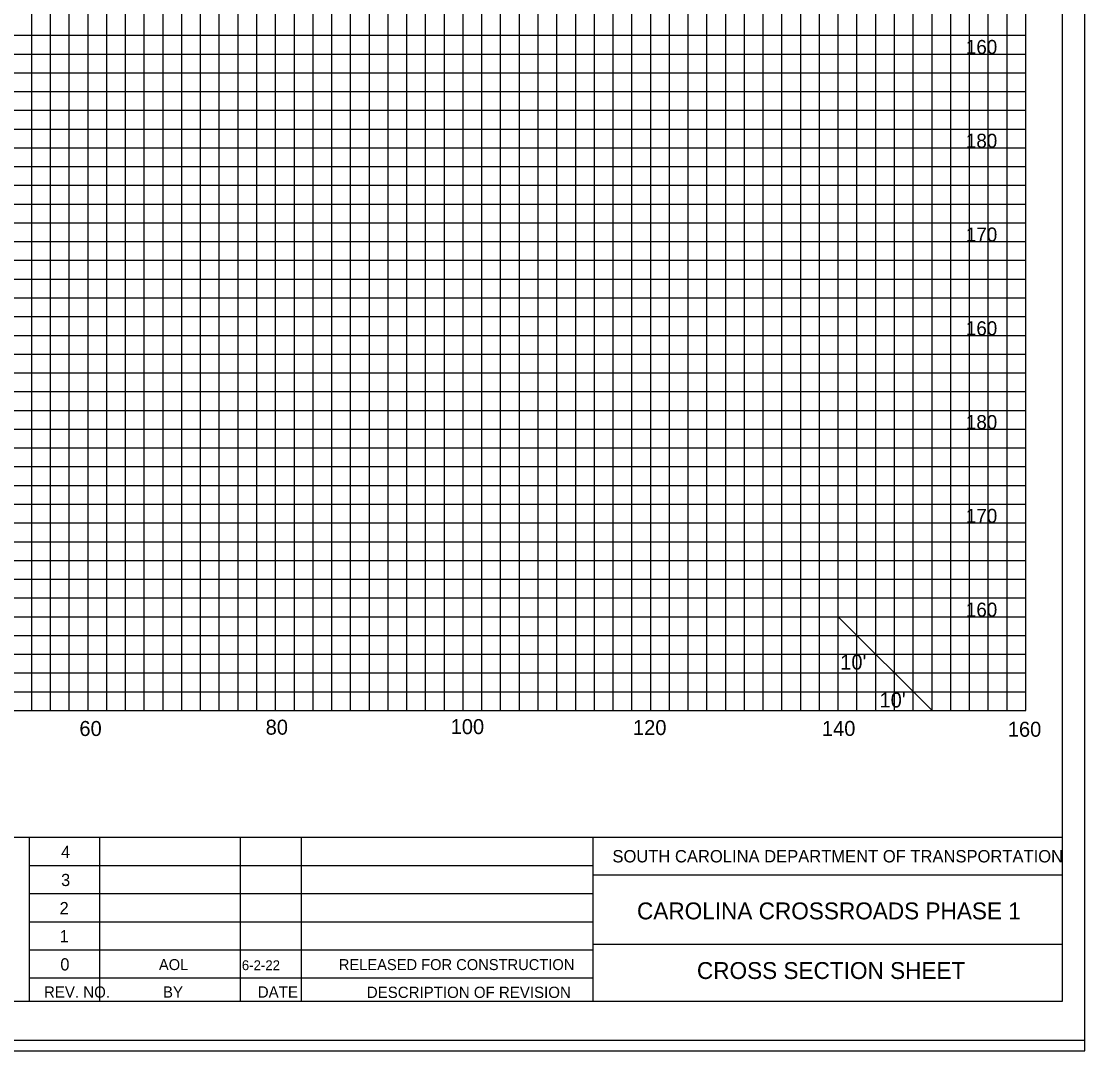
# Model space of a CAD drawing. Extents: x 967 to 1326, y 964 to 2864.
# Drawn here: x 1212.9 to 1326.3, y 2363.7 to 2473.5 of the extents above; entities that cross this region are included whole.
import ezdxf

# ---------------------------------------------------------------- set-up
doc = ezdxf.new("R2010")
doc.units = 0
for name, color, linetype in [('Default', 7, 'Continuous'), ('RD_EX_RW', 7, 'Continuous'), ('RD_PD_Final_TX', 7, 'Continuous'), ('RD_SHT_ShtClip', 7, 'Continuous'), ('RD_XS_TX_Elev_PR', 7, 'Continuous'), ('RD_XS_TX_ShdSlope', 7, 'Continuous'), ('RD_XS_TX_Slope', 7, 'Continuous')]:
    doc.layers.add(name, color=color, linetype=linetype)

msp = doc.modelspace()

# ---------------------------------------------------------------- linework, layer by layer
at = {"layer": 'RD_EX_RW'}
for p, q in [((1220, 2400), (1220, 2570)), ((1230, 2400), (1230, 2570)), ((1240, 2400), (1240, 2570)), ((1250, 2400), (1250, 2570)), ((1260, 2400), (1260, 2570)), ((1270, 2400), (1270, 2570)), ((1280, 2400), (1280, 2570)), ((1290, 2400), (1290, 2570)), ((1300, 2400), (1300, 2570)), ((1310, 2400), (1310, 2570)), ((1320, 2400), (1320, 2570)), ((1000, 2470), (1320, 2470)), ((1000, 2460), (1320, 2460)), ((1000, 2450), (1320, 2450)), ((1000, 2440), (1320, 2440)), ((1000, 2430), (1320, 2430)), ((1000, 2420), (1320, 2420)), ((1000, 2410), (1320, 2410)), ((1000, 2400), (1320, 2400))]:
    msp.add_line(p, q, dxfattribs=at)
at = {"layer": 'RD_PD_Final_TX'}
for p, q in [((1323.89, 2578.46), (1323.89, 2368.98)), ((996.11, 2386.49), (1323.89, 2386.49)), ((1213.76, 2368.94), (1213.76, 2386.49)), ((1221.26, 2368.95), (1221.26, 2386.48)), ((1236.26, 2368.95), (1236.26, 2386.48)), ((1242.76, 2368.95), (1242.76, 2386.48)), ((1273.88, 2368.98), (1273.88, 2386.49)), ((1213.76, 2383.48), (1273.88, 2383.48)), ((1323.93, 2382.43), (1273.88, 2382.43)), ((1213.76, 2380.48), (1273.88, 2380.48)), ((1213.76, 2377.48), (1273.88, 2377.48)), ((1323.89, 2375.04), (1273.88, 2375.04)), ((1213.76, 2374.48), (1273.88, 2374.48)), ((1213.76, 2371.48), (1273.88, 2371.48)), ((1323.89, 2368.98), (996.11, 2368.98))]:
    msp.add_line(p, q, dxfattribs=at)
at = {"layer": 'RD_SHT_ShtClip'}
for p, q in [((1214, 2400), (1214, 2570)), ((1216, 2400), (1216, 2570)), ((1218, 2400), (1218, 2570)), ((1222, 2400), (1222, 2570)), ((1224, 2400), (1224, 2570)), ((1226, 2400), (1226, 2570)), ((1228, 2400), (1228, 2570)), ((1232, 2400), (1232, 2570)), ((1234, 2400), (1234, 2570)), ((1236, 2400), (1236, 2570)), ((1238, 2400), (1238, 2570)), ((1242, 2400), (1242, 2570)), ((1244, 2400), (1244, 2570)), ((1246, 2400), (1246, 2570)), ((1248, 2400), (1248, 2570)), ((1252, 2400), (1252, 2570)), ((1254, 2400), (1254, 2570)), ((1256, 2400), (1256, 2570)), ((1258, 2400), (1258, 2570)), ((1262, 2400), (1262, 2570)), ((1264, 2400), (1264, 2570)), ((1266, 2400), (1266, 2570)), ((1268, 2400), (1268, 2570)), ((1272, 2400), (1272, 2570)), ((1274, 2400), (1274, 2570)), ((1276, 2400), (1276, 2570)), ((1278, 2400), (1278, 2570)), ((1282, 2400), (1282, 2570)), ((1284, 2400), (1284, 2570)), ((1286, 2400), (1286, 2570)), ((1288, 2400), (1288, 2570)), ((1292, 2400), (1292, 2570)), ((1294, 2400), (1294, 2570)), ((1296, 2400), (1296, 2570)), ((1298, 2400), (1298, 2570)), ((1302, 2400), (1302, 2570)), ((1304, 2400), (1304, 2570)), ((1306, 2400), (1306, 2570)), ((1308, 2400), (1308, 2570)), ((1312, 2400), (1312, 2570)), ((1314, 2400), (1314, 2570)), ((1316, 2400), (1316, 2570)), ((1318, 2400), (1318, 2570)), ((1000, 2472), (1320, 2472)), ((1000, 2468), (1320, 2468)), ((1000, 2466), (1320, 2466)), ((1000, 2464), (1320, 2464)), ((1000, 2462), (1320, 2462)), ((1000, 2458), (1320, 2458)), ((1000, 2456), (1320, 2456)), ((1000, 2454), (1320, 2454)), ((1000, 2452), (1320, 2452)), ((1000, 2448), (1320, 2448)), ((1000, 2446), (1320, 2446)), ((1000, 2444), (1320, 2444)), ((1000, 2442), (1320, 2442)), ((1000, 2438), (1320, 2438)), ((1000, 2436), (1320, 2436)), ((1000, 2434), (1320, 2434)), ((1000, 2432), (1320, 2432)), ((1000, 2428), (1320, 2428)), ((1000, 2426), (1320, 2426)), ((1000, 2424), (1320, 2424)), ((1000, 2422), (1320, 2422)), ((1000, 2418), (1320, 2418)), ((1000, 2416), (1320, 2416)), ((1000, 2414), (1320, 2414)), ((1000, 2412), (1320, 2412)), ((1000, 2408), (1320, 2408)), ((1000, 2406), (1320, 2406)), ((1000, 2404), (1320, 2404)), ((1000, 2402), (1320, 2402))]:
    msp.add_line(p, q, dxfattribs=at)
at = {"layer": 'RD_XS_TX_Elev_PR'}
for points in [[(967.41, 2363.72), (1326.28, 2363.72), (1326.28, 2583.72), (967.41, 2583.72)], [(988.52, 2364.84), (1326.28, 2364.84), (1326.28, 2582.6), (988.52, 2582.6)]]:
    msp.add_lwpolyline(points, close=True, dxfattribs=at)
at = {"layer": 'RD_XS_TX_Slope'}
msp.add_line((1300, 2410), (1310, 2400), dxfattribs=at)

# ---------------------------------------------------------------- texts
at = {"layer": 'Default'}
for s, p in [('160', (1313.61, 2470)), ('180', (1313.61, 2460)), ('170', (1313.61, 2450)), ('160', (1313.61, 2440)), ('180', (1313.61, 2430)), ('170', (1313.61, 2420)), ('160', (1313.61, 2410))]:
    msp.add_text(s, height=1.5, dxfattribs=at).set_placement(p)
at = {"layer": 'RD_XS_TX_ShdSlope'}
for s, height, p in [('AOL', 1.17, (1227.56, 2372.32)), ('6-2-22', 1.053, (1236.4, 2372.31)), ('RELEASED FOR CONSTRUCTION', 1.17, (1246.74, 2372.32))]:
    msp.add_text(s, height=height, dxfattribs=at).set_placement(p)
at = {"layer": 'RD_XS_TX_Slope'}
for s, height, p in [("10'", 1.6, (1300.21, 2404.36)), ("10'", 1.6, (1304.4, 2400.32)), ('60', 1.6, (1219.08, 2397.28)), ('80', 1.6, (1238.94, 2397.42)), ('100', 1.6, (1258.67, 2397.48)), ('120', 1.6, (1278.11, 2397.38)), ('140', 1.6, (1298.26, 2397.29)), ('160', 1.6, (1318.08, 2397.2)), ('4', 1.3, (1217.13, 2384.28)), ('SOUTH CAROLINA DEPARTMENT OF TRANSPORTATION', 1.32, (1275.92, 2383.8)), ('3', 1.3, (1217.13, 2381.28)), ('2', 1.3, (1216.97, 2378.28)), ('1', 1.3, (1216.97, 2375.28)), ('0', 1.3, (1217.05, 2372.28)), ('REV. NO.', 1.2, (1215.3, 2369.38)), ('BY', 1.2, (1227.99, 2369.38)), ('DATE', 1.2, (1238.1, 2369.38)), ('DESCRIPTION OF REVISION', 1.2, (1249.73, 2369.35))]:
    msp.add_text(s, height=height, dxfattribs=at).set_placement(p)
for s, p in [('CAROLINA CROSSROADS PHASE 1', (1278.54, 2377.73)), ('CROSS SECTION SHEET', (1284.93, 2371.37))]:
    msp.add_text(s, height=1.8, rotation=0, dxfattribs=at).set_placement(p)

doc.saveas('drawing.dxf')
